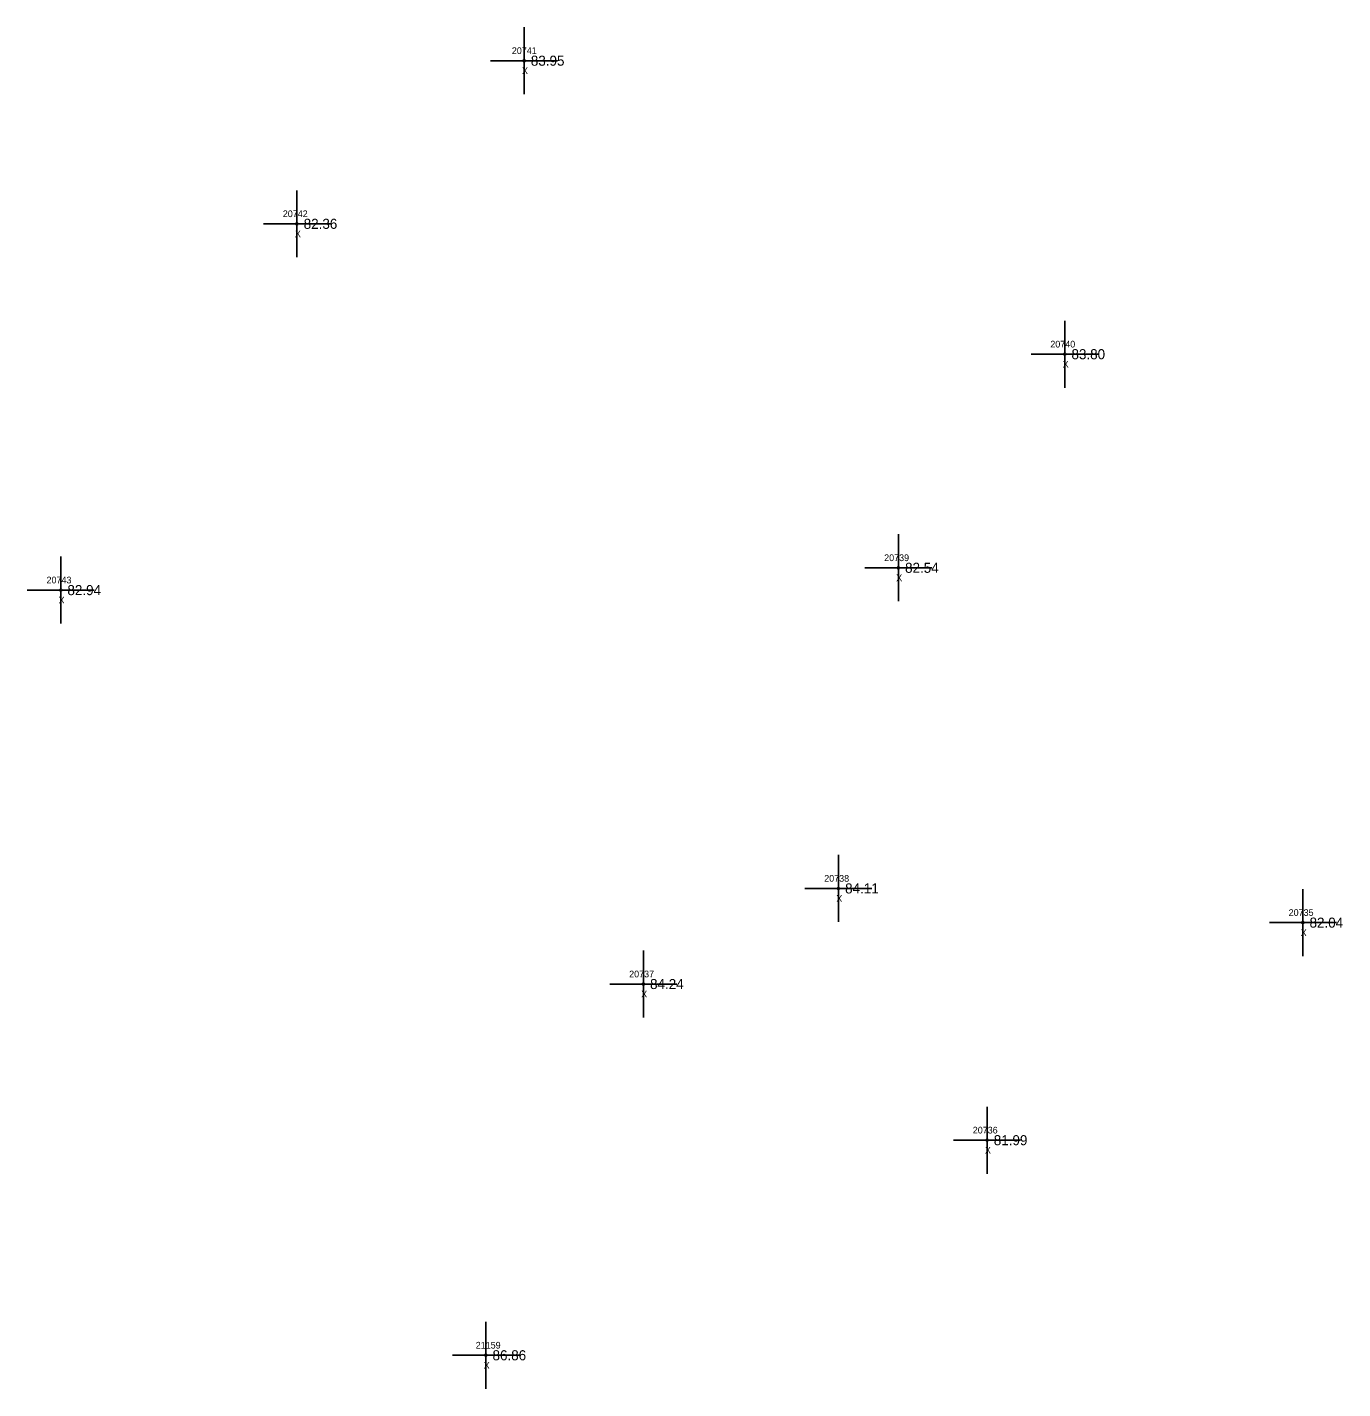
# Model space of a CAD drawing. Extents: x 2530197 to 2532051, y 935230 to 936631.
# Drawn here: x 2530730.4 to 2530926.8, y 936201.6 to 936404.9 of the extents above; entities that cross this region are included whole.
import ezdxf

# ---------------------------------------------------------------- set-up
doc = ezdxf.new("R2010")
doc.units = 0
for name, color, linetype in [('RD_EX_Misc', 7, 'Continuous'), ('RD_EX_Misc_txCode', 7, 'Continuous'), ('RD_EX_TX_Misc_ELEV', 7, 'Continuous'), ('RD_SMD_Locator', 7, 'Continuous')]:
    doc.layers.add(name, color=color, linetype=linetype)

msp = doc.modelspace()

# ---------------------------------------------------------------- linework, layer by layer
at = {"layer": 'RD_EX_Misc'}
for p, q in [((2530804.6, 936394.89), (2530804.6, 936404.89)), ((2530799.6, 936399.89), (2530809.6, 936399.89)), ((2530770.68, 936370.53), (2530770.68, 936380.53)), ((2530765.68, 936375.53), (2530775.68, 936375.53)), ((2530885.33, 936351.06), (2530885.33, 936361.06)), ((2530880.33, 936356.06), (2530890.33, 936356.06)), ((2530860.48, 936319.16), (2530860.48, 936329.16)), ((2530735.4, 936315.83), (2530735.4, 936325.83)), ((2530855.48, 936324.16), (2530865.48, 936324.16)), ((2530730.4, 936320.83), (2530740.4, 936320.83)), ((2530851.53, 936271.28), (2530851.53, 936281.28)), ((2530846.53, 936276.28), (2530856.53, 936276.28)), ((2530920.88, 936266.17), (2530920.88, 936276.17)), ((2530915.88, 936271.17), (2530925.88, 936271.17)), ((2530822.4, 936257), (2530822.4, 936267)), ((2530817.4, 936262), (2530827.4, 936262)), ((2530873.73, 936233.68), (2530873.73, 936243.68)), ((2530868.73, 936238.68), (2530878.73, 936238.68)), ((2530798.88, 936201.56), (2530798.88, 936211.56)), ((2530793.88, 936206.56), (2530803.88, 936206.56))]:
    msp.add_line(p, q, dxfattribs=at)
at = {"layer": 'RD_SMD_Locator'}
for centre in [(2530804.6, 936399.89), (2530770.68, 936375.53), (2530885.33, 936356.06), (2530860.48, 936324.16), (2530735.4, 936320.83), (2530851.53, 936276.28), (2530920.88, 936271.17), (2530822.4, 936262), (2530873.73, 936238.68), (2530798.88, 936206.56)]:
    msp.add_circle(centre, 0.15, dxfattribs=at)

# ---------------------------------------------------------------- texts
at = {"layer": 'RD_EX_Misc_txCode'}
for s, p in [('20741', (2530802.76, 936400.89)), ('X', (2530804.28, 936397.89)), ('20742', (2530768.56, 936376.53)), ('X', (2530770.37, 936373.53)), ('20740', (2530883.17, 936357.06)), ('X', (2530885.02, 936354.06)), ('20739', (2530858.36, 936325.16)), ('20743', (2530733.28, 936321.83)), ('X', (2530860.16, 936322.16)), ('X', (2530735.08, 936318.83)), ('20738', (2530849.41, 936277.28)), ('X', (2530851.21, 936274.28)), ('20735', (2530918.76, 936272.17)), ('X', (2530920.56, 936269.17)), ('20737', (2530820.28, 936263)), ('X', (2530822.08, 936260)), ('20736', (2530871.59, 936239.68)), ('X', (2530873.41, 936236.68)), ('21159', (2530797.37, 936207.56)), ('X', (2530798.56, 936204.56))]:
    msp.add_text(s, height=1, dxfattribs=at).set_placement(p)
at = {"layer": 'RD_EX_TX_Misc_ELEV'}
for s, p in [('83.95', (2530805.6, 936399.14)), ('82.36', (2530771.68, 936374.78)), ('83.80', (2530886.33, 936355.31)), ('82.54', (2530861.48, 936323.41)), ('82.94', (2530736.4, 936320.08)), ('84.11', (2530852.53, 936275.53)), ('82.04', (2530921.88, 936270.42)), ('84.24', (2530823.4, 936261.25)), ('81.99', (2530874.73, 936237.93)), ('86.86', (2530799.88, 936205.81))]:
    msp.add_text(s, height=1.5, dxfattribs=at).set_placement(p)

doc.saveas('drawing.dxf')
